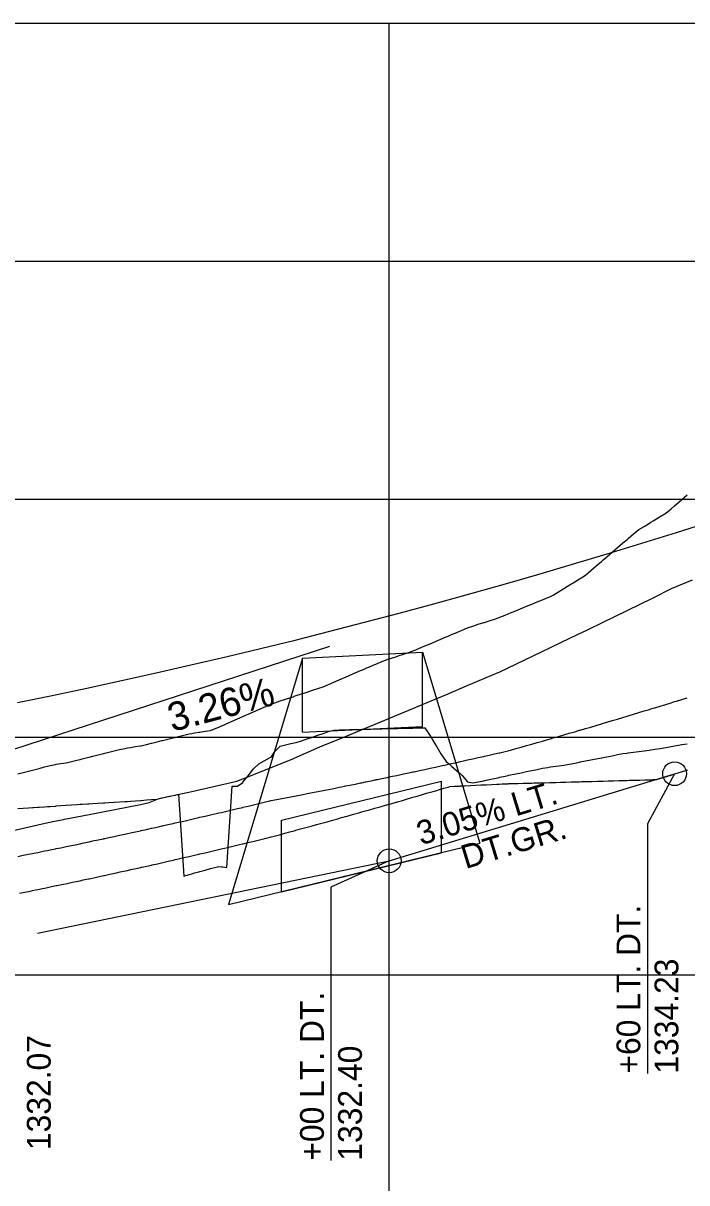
# Model space of a CAD drawing. Extents: x 1371206 to 1374178, y 379328 to 381511.
# Drawn here: x 1372567.7 to 1372707.2, y 379554.7 to 379798.4 of the extents above; entities that cross this region are included whole.
import ezdxf

# ---------------------------------------------------------------- set-up
doc = ezdxf.new("R2010")
doc.units = 0
for name, color, linetype in [('37', 7, 'Continuous'), ('R_Exist Surface', 7, 'Continuous'), ('R_Profile Work Left', 7, 'Continuous'), ('R_Profile Work Right', 7, 'Continuous'), ('R_Vert Alg', 7, 'Continuous'), ('R_Vert Alg Annot', 7, 'Continuous')]:
    doc.layers.add(name, color=color, linetype=linetype)

msp = doc.modelspace()

# ---------------------------------------------------------------- linework, layer by layer
at = {"layer": '37'}
for p, q in [((1371244.63, 379798.35), (1374144.63, 379798.35)), ((1371244.63, 379798.35), (1374144.63, 379798.35)), ((1372644.63, 379348.35), (1372644.63, 379798.35)), ((1371244.63, 379748.35), (1374144.63, 379748.35)), ((1371244.63, 379698.35), (1374144.63, 379698.35)), ((1371244.63, 379648.35), (1374144.63, 379648.35)), ((1371244.63, 379598.35), (1372944.63, 379598.35)), ((1371244.63, 379598.35), (1374144.63, 379598.35))]:
    msp.add_line(p, q, dxfattribs=at)
at = {"layer": 'R_Exist Surface'}
msp.add_lwpolyline([(1372560.01, 379627.48), (1372570.79, 379629.89), (1372573.58, 379630.53), (1372576.16, 379631.02), (1372576.38, 379631.07), (1372581.56, 379632.08), (1372592.34, 379634.21), (1372594.2, 379634.59), (1372596.3, 379635.42), (1372603.11, 379636.93), (1372612.61, 379639.07), (1372613.89, 379639.58), (1372624.59, 379643.86), (1372624.66, 379643.89), (1372630.05, 379646.26), (1372635.44, 379648.46), (1372640.47, 379650.55), (1372645.72, 379652.71), (1372646.21, 379652.92), (1372654.3, 379656.3), (1372656.99, 379657.43), (1372660.89, 379659.08), (1372667.54, 379661.9), (1372667.76, 379662), (1372678.54, 379667.15), (1372682.76, 379669.2), (1372686.44, 379670.97), (1372689.31, 379672.36), (1372700.09, 379677.63), (1372703.95, 379679.54), (1372708.38, 379681.37)], dxfattribs=at)
at = {"layer": 'R_Profile Work Left'}
for p, q in [((1372626.42, 379664.94), (1372610.88, 379613.15)), ((1372626.42, 379664.94), (1372651.63, 379666.17)), ((1372626.42, 379649.34), (1372626.42, 379664.94)), ((1372651.63, 379650.57), (1372651.63, 379666.17)), ((1372651.63, 379666.17), (1372663.67, 379626.02)), ((1372626.42, 379649.34), (1372651.63, 379650.57)), ((1372621.96, 379630.85), (1372655.59, 379639.05)), ((1372655.59, 379624.05), (1372655.59, 379639.05)), ((1372621.96, 379615.85), (1372621.96, 379630.85)), ((1372610.88, 379613.15), (1372663.67, 379626.02)), ((1372621.96, 379615.85), (1372655.59, 379624.05))]:
    msp.add_line(p, q, dxfattribs=at)
for points in [[(1372611.59, 379638.05), (1372612.72, 379638.01), (1372613.84, 379638.81), (1372613.89, 379638.87), (1372614.63, 379639.81), (1372614.97, 379640.23), (1372616.09, 379641.65), (1372617.22, 379642.75), (1372618.34, 379643.35), (1372619.47, 379643.96), (1372619.63, 379644.05), (1372619.79, 379644.14), (1372620.6, 379645.29), (1372621.72, 379646.46), (1372622.85, 379646.72), (1372623.97, 379646.97), (1372624.63, 379647.12), (1372624.66, 379647.13), (1372625.1, 379647.22), (1372626.22, 379647.58), (1372627.35, 379647.96), (1372628.47, 379648.34), (1372629.6, 379648.72), (1372629.63, 379648.73), (1372630.72, 379649.1), (1372631.85, 379649.48), (1372632.97, 379649.82), (1372634.1, 379649.85), (1372634.63, 379649.86), (1372635.23, 379649.88), (1372635.44, 379649.89), (1372636.35, 379649.91), (1372637.48, 379649.94), (1372638.6, 379649.97), (1372638.85, 379649.98), (1372639.63, 379650), (1372639.73, 379650.01), (1372640.85, 379650.04), (1372641.39, 379650.05), (1372641.63, 379650.06), (1372641.83, 379650.06), (1372641.98, 379650.07), (1372642.14, 379650.07), (1372643.1, 379650.09), (1372644.23, 379650.12), (1372644.63, 379650.13), (1372645.35, 379650.15), (1372646.21, 379650.16), (1372646.48, 379650.17), (1372647.6, 379650.2), (1372648.73, 379650.23), (1372649.63, 379650.25), (1372649.86, 379650.26), (1372650.98, 379650.29), (1372652.11, 379650.32), (1372653.23, 379648.59), (1372654.36, 379646.71), (1372654.63, 379646.26), (1372655.48, 379644.84), (1372656.61, 379643.22), (1372656.99, 379642.89), (1372657.73, 379642.25), (1372658.86, 379641.27), (1372659.63, 379640.6), (1372659.98, 379640.3), (1372661.11, 379638.93), (1372662.23, 379638.72), (1372663.36, 379638.94), (1372664.49, 379639.18), (1372664.63, 379639.21), (1372665.61, 379639.42), (1372666.74, 379639.66), (1372667.76, 379639.88), (1372667.86, 379639.9), (1372668.99, 379640.14), (1372669.63, 379640.28), (1372669.79, 379640.31), (1372670.11, 379640.38), (1372671.24, 379640.62), (1372672.36, 379640.85), (1372673.49, 379641.08), (1372674.61, 379641.32), (1372674.63, 379641.32), (1372675.74, 379641.55), (1372676.87, 379641.79), (1372677.99, 379641.98), (1372678.54, 379642.06), (1372679.12, 379642.14), (1372679.63, 379642.22), (1372680.24, 379642.3), (1372681.37, 379642.47), (1372682.49, 379642.66), (1372683.62, 379642.89), (1372684.63, 379643.08), (1372684.74, 379643.11), (1372685.87, 379643.33), (1372686.99, 379643.55), (1372688.12, 379643.77), (1372689.24, 379643.99), (1372689.31, 379644), (1372689.63, 379644.06), (1372690.37, 379644.21), (1372691.5, 379644.43), (1372692.62, 379644.65), (1372693.75, 379644.86), (1372694.63, 379644.98), (1372694.87, 379645.01), (1372696, 379645.17), (1372697.12, 379645.32), (1372698.25, 379645.47), (1372699.37, 379645.62), (1372699.63, 379645.65), (1372700.09, 379645.72), (1372700.5, 379645.77), (1372701.62, 379645.92), (1372702.75, 379646.13), (1372703.87, 379646.33), (1372704.63, 379646.47), (1372705, 379646.54), (1372706.13, 379646.75), (1372707.25, 379646.95)], [(1372566.92, 379615.54), (1372568.04, 379615.76), (1372569.15, 379615.99), (1372569.63, 379616.09), (1372570.27, 379616.22), (1372570.79, 379616.33), (1372571.1, 379616.39), (1372571.38, 379616.45), (1372572.5, 379616.68), (1372573.61, 379616.91), (1372574.63, 379617.12), (1372574.73, 379617.14), (1372575.84, 379617.37), (1372576.96, 379617.61), (1372578.07, 379617.84), (1372579.18, 379618.08), (1372579.63, 379618.17), (1372580.3, 379618.32), (1372581.41, 379618.55), (1372581.56, 379618.59), (1372581.88, 379618.66), (1372582.53, 379618.79), (1372583.64, 379619.03), (1372584.63, 379619.25), (1372584.76, 379619.28), (1372585.87, 379619.52), (1372586.99, 379619.76), (1372588.1, 379620), (1372589.22, 379620.25), (1372589.63, 379620.34), (1372590.33, 379620.5), (1372591.45, 379620.74), (1372592.34, 379620.94), (1372592.56, 379620.99), (1372592.66, 379621.01), (1372593.68, 379621.24), (1372594.63, 379621.45), (1372594.79, 379621.49), (1372595.9, 379621.74), (1372597.02, 379621.99), (1372598.13, 379622.25), (1372599.25, 379622.5), (1372599.63, 379622.59), (1372600.36, 379622.76), (1372601.48, 379623.01), (1372602.59, 379623.27), (1372603.11, 379623.39), (1372603.44, 379623.47), (1372603.71, 379623.53), (1372604.63, 379623.74), (1372604.82, 379623.79), (1372605.94, 379624.05), (1372607.05, 379624.31), (1372608.17, 379624.57), (1372609.28, 379624.83), (1372609.63, 379624.92), (1372610.39, 379625.1), (1372611.51, 379625.36), (1372612.62, 379625.63), (1372613.74, 379625.9), (1372613.89, 379625.93), (1372614.23, 379626.01), (1372614.63, 379626.11), (1372614.85, 379626.16), (1372615.97, 379626.43), (1372617.08, 379626.7), (1372618.2, 379626.98), (1372619.31, 379627.25), (1372619.63, 379627.33), (1372619.79, 379627.37), (1372620.43, 379627.54), (1372621.54, 379627.83), (1372622.66, 379628.13), (1372623.77, 379628.43), (1372624.63, 379628.67), (1372624.66, 379628.67), (1372624.89, 379628.73), (1372625.01, 379628.77), (1372626, 379629.04), (1372627.11, 379629.34), (1372628.23, 379629.64), (1372629.34, 379629.95), (1372629.63, 379630.03), (1372630.46, 379630.26), (1372631.57, 379630.56), (1372632.69, 379630.87), (1372633.8, 379631.18), (1372634.63, 379631.41), (1372634.92, 379631.49), (1372635.44, 379631.64), (1372635.79, 379631.74), (1372636.03, 379631.8), (1372637.15, 379632.12), (1372638.26, 379632.43), (1372638.85, 379632.6), (1372639.38, 379632.74), (1372639.63, 379632.82), (1372639.94, 379632.91), (1372640.49, 379633.06), (1372641.39, 379633.31), (1372641.6, 379633.38), (1372641.63, 379633.38), (1372642.14, 379633.53), (1372642.72, 379633.69), (1372643.83, 379634.01), (1372644.63, 379634.24), (1372644.95, 379634.33), (1372646.06, 379634.65), (1372646.21, 379634.7), (1372646.57, 379634.8), (1372647.18, 379634.97), (1372648.29, 379635.3), (1372649.41, 379635.62), (1372649.63, 379635.69), (1372650.52, 379635.94), (1372651.64, 379636.27), (1372652.75, 379636.6), (1372653.87, 379636.92), (1372654.63, 379637.15), (1372654.98, 379637.25), (1372656.1, 379637.58), (1372656.99, 379637.85), (1372657.21, 379637.91), (1372657.35, 379637.96), (1372658.32, 379638), (1372659.44, 379638.06), (1372659.63, 379638.07), (1372660.55, 379638.11), (1372661.67, 379638.17), (1372662.78, 379638.22), (1372663.9, 379638.28), (1372664.63, 379638.31), (1372665.01, 379638.33), (1372666.13, 379638.38), (1372667.24, 379638.44), (1372667.76, 379638.46), (1372668.36, 379638.49), (1372669.47, 379638.54), (1372669.63, 379638.55), (1372669.79, 379638.56), (1372670.59, 379638.58), (1372671.7, 379638.61), (1372672.82, 379638.64), (1372673.93, 379638.67), (1372674.63, 379638.69), (1372675.04, 379638.7), (1372676.16, 379638.73), (1372677.27, 379638.76), (1372678.39, 379638.79), (1372678.54, 379638.8), (1372679.5, 379638.82), (1372679.63, 379638.83), (1372680.62, 379638.85), (1372681.73, 379638.88), (1372682.85, 379638.91), (1372683.96, 379638.95), (1372684.63, 379638.96), (1372685.08, 379638.98), (1372686.19, 379639.01), (1372687.31, 379639.04), (1372688.42, 379639.07), (1372689.31, 379639.1), (1372689.53, 379639.1), (1372689.63, 379639.1), (1372690.65, 379639.13), (1372691.76, 379639.17), (1372692.88, 379639.2), (1372693.99, 379639.23), (1372694.63, 379639.25), (1372695.11, 379639.26), (1372696.22, 379639.29), (1372697.34, 379639.32), (1372698.45, 379639.36), (1372699.57, 379639.39), (1372699.63, 379639.39), (1372700.09, 379639.4), (1372700.68, 379639.42), (1372700.84, 379639.43), (1372701.8, 379639.72), (1372702.91, 379640.07), (1372704.03, 379640.42), (1372704.63, 379640.61), (1372705.14, 379640.77), (1372706.25, 379641.12), (1372707.37, 379641.47)], [(1372600.34, 379636.33), (1372601.46, 379619.15), (1372602.59, 379619.5), (1372603.11, 379619.64), (1372603.71, 379619.8), (1372604.63, 379620.04), (1372604.84, 379620.1), (1372605.96, 379620.4), (1372607.09, 379620.7), (1372608.22, 379621.01), (1372608.83, 379621.17), (1372609.34, 379621.1), (1372609.63, 379621.06), (1372610.47, 379620.95), (1372611.59, 379638.05)], [(1372566.58, 379633.35), (1372567.7, 379633.42), (1372568.83, 379633.49), (1372569.63, 379633.54), (1372569.95, 379633.56), (1372570.79, 379633.61), (1372571.08, 379633.63), (1372572.2, 379633.69), (1372572.83, 379633.73), (1372573.33, 379633.77), (1372574.45, 379633.86), (1372574.63, 379633.88), (1372575.58, 379633.96), (1372576.7, 379634.04), (1372577.83, 379634.11), (1372578.96, 379634.18), (1372579.63, 379634.22), (1372580.08, 379634.25), (1372581.21, 379634.32), (1372581.56, 379634.34), (1372582.33, 379634.39), (1372583.46, 379634.46), (1372584.58, 379634.53), (1372584.63, 379634.53), (1372584.83, 379634.55), (1372585.71, 379634.6), (1372586.83, 379634.67), (1372587.96, 379634.74), (1372589.08, 379634.81), (1372589.63, 379634.84), (1372590.21, 379634.88), (1372591.33, 379634.95), (1372592.34, 379635.03), (1372592.46, 379635.04), (1372593.59, 379635.13), (1372594.63, 379635.22), (1372594.71, 379635.23), (1372595.84, 379635.32), (1372596.83, 379635.55), (1372596.96, 379635.57), (1372598.09, 379635.83), (1372599.21, 379636.08), (1372599.63, 379636.17), (1372600.34, 379636.33)]]:
    msp.add_lwpolyline(points, dxfattribs=at)
at = {"layer": 'R_Profile Work Right'}
for points in [[(1372566.58, 379640.63), (1372567.7, 379640.91), (1372568.83, 379641.2), (1372569.63, 379641.41), (1372569.95, 379641.49), (1372570.79, 379641.7), (1372571.08, 379641.77), (1372572.2, 379642.06), (1372572.83, 379642.22), (1372573.33, 379642.35), (1372574.45, 379642.59), (1372574.63, 379642.62), (1372575.58, 379642.78), (1372576.7, 379642.96), (1372577.83, 379643.21), (1372578.96, 379643.49), (1372579.63, 379643.66), (1372580.08, 379643.77), (1372581.21, 379644.05), (1372581.56, 379644.14), (1372582.33, 379644.33), (1372583.46, 379644.61), (1372584.58, 379644.89), (1372584.63, 379644.91), (1372584.83, 379644.96), (1372585.71, 379645.17), (1372586.83, 379645.45), (1372587.96, 379645.74), (1372589.08, 379645.97), (1372589.63, 379646.05), (1372590.21, 379646.15), (1372591.33, 379646.33), (1372592.34, 379646.5), (1372592.46, 379646.53), (1372593.59, 379646.8), (1372594.63, 379647.06), (1372594.71, 379647.08), (1372595.84, 379647.35), (1372596.83, 379647.6), (1372596.96, 379647.63), (1372598.09, 379647.9), (1372599.21, 379648.18), (1372599.63, 379648.28), (1372600.34, 379648.45), (1372601.46, 379648.73), (1372602.59, 379649), (1372603.11, 379649.11), (1372603.71, 379649.21), (1372604.63, 379649.35), (1372604.84, 379649.38), (1372605.96, 379649.55), (1372607.09, 379649.73), (1372608.22, 379650.19), (1372608.83, 379650.46), (1372609.34, 379650.68), (1372609.63, 379650.81), (1372610.47, 379651.17), (1372611.59, 379651.67), (1372612.72, 379652.16), (1372613.84, 379652.65), (1372613.89, 379652.67), (1372614.63, 379652.99), (1372614.97, 379653.14), (1372616.09, 379653.63), (1372617.22, 379654.12), (1372618.34, 379654.61), (1372619.47, 379655.1), (1372619.63, 379655.17), (1372619.79, 379655.24), (1372620.6, 379655.55), (1372621.72, 379655.93), (1372622.85, 379656.3), (1372623.97, 379656.68), (1372624.63, 379656.89), (1372624.66, 379656.91), (1372625.1, 379657.05), (1372626.22, 379657.42), (1372627.35, 379657.8), (1372628.47, 379658.17), (1372629.6, 379658.54), (1372629.63, 379658.55), (1372630.72, 379658.92), (1372631.85, 379659.39), (1372632.97, 379659.88), (1372634.1, 379660.37), (1372634.63, 379660.59), (1372635.23, 379660.85), (1372635.44, 379660.94), (1372636.35, 379661.34), (1372637.48, 379661.82), (1372638.6, 379662.3), (1372638.85, 379662.41), (1372639.63, 379662.75), (1372639.73, 379662.79), (1372640.85, 379663.27), (1372641.39, 379663.5), (1372641.63, 379663.61), (1372641.83, 379663.69), (1372641.98, 379663.75), (1372642.14, 379663.82), (1372643.1, 379664.24), (1372644.23, 379664.65), (1372644.63, 379664.78), (1372645.35, 379665.02), (1372646.21, 379665.3), (1372646.48, 379665.38), (1372647.6, 379665.75), (1372648.73, 379666.12), (1372649.63, 379666.45), (1372649.86, 379666.54), (1372650.98, 379667.02), (1372652.11, 379667.5), (1372653.23, 379667.97), (1372654.36, 379668.45), (1372654.63, 379668.56), (1372655.48, 379668.92), (1372656.61, 379669.4), (1372656.99, 379669.56), (1372657.73, 379669.87), (1372658.86, 379670.35), (1372659.63, 379670.67), (1372659.98, 379670.82), (1372661.11, 379671.3), (1372662.23, 379671.68), (1372663.36, 379672.04), (1372664.49, 379672.4), (1372664.63, 379672.45), (1372665.61, 379672.77), (1372666.74, 379673.13), (1372667.76, 379673.47), (1372667.86, 379673.51), (1372668.99, 379673.98), (1372669.63, 379674.25), (1372669.79, 379674.31), (1372670.11, 379674.44), (1372671.24, 379674.9), (1372672.36, 379675.36), (1372673.49, 379675.82), (1372674.61, 379676.28), (1372674.63, 379676.28), (1372675.74, 379676.73), (1372676.87, 379677.19), (1372677.99, 379677.65), (1372678.54, 379677.87), (1372679.12, 379678.16), (1372679.63, 379678.48), (1372680.24, 379678.86), (1372681.37, 379679.55), (1372682.49, 379680.24), (1372683.62, 379680.94), (1372684.63, 379681.56), (1372684.74, 379681.63), (1372685.87, 379682.37), (1372686.99, 379683.34), (1372688.12, 379684.31), (1372689.24, 379685.27), (1372689.31, 379685.33), (1372689.63, 379685.6), (1372690.37, 379686.24), (1372691.5, 379687.2), (1372692.62, 379688.17), (1372693.75, 379689.13), (1372694.63, 379689.89), (1372694.87, 379690.1), (1372696, 379691.06), (1372697.12, 379691.93), (1372698.25, 379692.62), (1372699.37, 379693.31), (1372699.63, 379693.47), (1372700.09, 379693.75), (1372700.5, 379694), (1372701.62, 379694.69), (1372702.75, 379695.38), (1372703.87, 379696.31), (1372704.63, 379696.96), (1372705, 379697.29), (1372706.13, 379698.26), (1372707.25, 379699.24)], [(1372566.58, 379623.27), (1372567.7, 379623.5), (1372568.83, 379623.72), (1372569.63, 379623.89), (1372569.95, 379623.95), (1372570.79, 379624.12), (1372571.08, 379624.18), (1372572.2, 379624.41), (1372572.83, 379624.53), (1372573.33, 379624.64), (1372574.45, 379624.87), (1372574.63, 379624.9), (1372575.58, 379625.1), (1372576.7, 379625.33), (1372577.83, 379625.56), (1372578.96, 379625.8), (1372579.63, 379625.94), (1372580.08, 379626.03), (1372581.21, 379626.27), (1372581.56, 379626.35), (1372582.33, 379626.51), (1372583.46, 379626.75), (1372584.58, 379626.99), (1372584.63, 379627), (1372584.83, 379627.04), (1372585.71, 379627.23), (1372586.83, 379627.47), (1372587.96, 379627.71), (1372589.08, 379627.96), (1372589.63, 379628.08), (1372590.21, 379628.2), (1372591.33, 379628.45), (1372592.34, 379628.67), (1372592.46, 379628.69), (1372593.59, 379628.94), (1372594.63, 379629.17), (1372594.71, 379629.19), (1372595.84, 379629.44), (1372596.83, 379629.66), (1372596.96, 379629.69), (1372598.09, 379629.94), (1372599.21, 379630.2), (1372599.63, 379630.29), (1372600.34, 379630.45), (1372601.46, 379630.7), (1372602.59, 379630.96), (1372603.11, 379631.08), (1372603.71, 379631.22), (1372604.63, 379631.43), (1372604.84, 379631.48), (1372605.96, 379631.73), (1372607.09, 379631.99), (1372608.22, 379632.25), (1372608.83, 379632.4), (1372609.34, 379632.52), (1372609.63, 379632.58), (1372610.47, 379632.78), (1372611.59, 379633.04), (1372612.72, 379633.31), (1372613.84, 379633.57), (1372613.89, 379633.59), (1372614.63, 379633.76), (1372614.97, 379633.84), (1372616.09, 379634.11), (1372617.22, 379634.38), (1372618.34, 379634.65), (1372619.47, 379634.92), (1372619.63, 379634.96), (1372619.79, 379635), (1372620.6, 379635.15), (1372621.72, 379635.36), (1372622.85, 379635.58), (1372623.97, 379635.8), (1372624.63, 379635.93), (1372624.66, 379635.93), (1372625.1, 379636.02), (1372626.22, 379636.24), (1372627.35, 379636.46), (1372628.47, 379636.68), (1372629.6, 379636.9), (1372629.63, 379636.91), (1372630.72, 379637.12), (1372631.85, 379637.35), (1372632.97, 379637.57), (1372634.1, 379637.8), (1372634.63, 379637.91), (1372635.23, 379638.03), (1372635.44, 379638.07), (1372636.35, 379638.25), (1372637.48, 379638.48), (1372638.6, 379638.71), (1372638.85, 379638.76), (1372639.63, 379638.92), (1372639.73, 379638.94), (1372640.85, 379639.18), (1372641.39, 379639.29), (1372641.63, 379639.34), (1372641.83, 379639.38), (1372641.98, 379639.41), (1372642.14, 379639.44), (1372643.1, 379639.64), (1372644.23, 379639.88), (1372644.63, 379639.96), (1372645.35, 379640.12), (1372646.21, 379640.3), (1372646.48, 379640.35), (1372647.6, 379640.59), (1372648.73, 379640.83), (1372649.63, 379641.02), (1372649.86, 379641.07), (1372650.98, 379641.31), (1372652.11, 379641.56), (1372653.23, 379641.8), (1372654.36, 379642.04), (1372654.63, 379642.1), (1372655.48, 379642.29), (1372656.61, 379642.54), (1372656.99, 379642.62), (1372657.73, 379642.78), (1372658.86, 379643.03), (1372659.63, 379643.2), (1372659.98, 379643.28), (1372661.11, 379643.53), (1372662.23, 379643.78), (1372663.36, 379644.03), (1372664.49, 379644.29), (1372664.63, 379644.32), (1372665.61, 379644.54), (1372666.74, 379644.8), (1372667.76, 379645.03), (1372667.86, 379645.05), (1372668.99, 379645.31), (1372669.63, 379645.46), (1372669.79, 379645.5), (1372670.11, 379645.6), (1372671.24, 379645.91), (1372672.36, 379646.23), (1372673.49, 379646.55), (1372674.61, 379646.87), (1372674.63, 379646.88), (1372675.74, 379647.19), (1372676.87, 379647.51), (1372677.99, 379647.84), (1372678.54, 379648), (1372679.12, 379648.16), (1372679.63, 379648.31), (1372680.24, 379648.49), (1372681.37, 379648.81), (1372682.49, 379649.14), (1372683.62, 379649.47), (1372684.63, 379649.77), (1372684.74, 379649.8), (1372685.87, 379650.13), (1372686.99, 379650.46), (1372688.12, 379650.79), (1372689.24, 379651.13), (1372689.31, 379651.15), (1372689.63, 379651.24), (1372690.37, 379651.46), (1372691.5, 379651.8), (1372692.62, 379652.13), (1372693.75, 379652.47), (1372694.63, 379652.74), (1372694.87, 379652.81), (1372696, 379653.15), (1372697.12, 379653.49), (1372698.25, 379653.83), (1372699.37, 379654.17), (1372699.63, 379654.25), (1372700.09, 379654.39), (1372700.5, 379654.52), (1372701.62, 379654.86), (1372702.75, 379655.21), (1372703.87, 379655.55), (1372704.63, 379655.79), (1372705, 379655.9), (1372706.13, 379656.25), (1372707.25, 379656.6)]]:
    msp.add_lwpolyline(points, dxfattribs=at)
at = {"layer": 'R_Vert Alg'}
for p, q in [((1372544.63, 379638.95), (1372632.13, 379667.48)), ((1372644.63, 379622.35), (1372704.63, 379640.65)), ((1372570.69, 379607.13), (1372644.63, 379622.35))]:
    msp.add_line(p, q, dxfattribs=at)
msp.add_lwpolyline([(1372566.51, 379655.58), (1372573.8, 379657.08), (1372581.09, 379658.62), (1372588.38, 379660.2), (1372595.67, 379661.82), (1372602.96, 379663.49), (1372610.26, 379665.19), (1372617.55, 379666.95), (1372624.84, 379668.74), (1372632.13, 379670.58), (1372639.42, 379672.46), (1372646.71, 379674.39), (1372654.01, 379676.36), (1372661.3, 379678.37), (1372668.59, 379680.42), (1372675.88, 379682.52), (1372683.17, 379684.66), (1372690.46, 379686.84), (1372697.76, 379689.07), (1372705.05, 379691.34), (1372712.34, 379693.65), (1372719.63, 379696.01)], dxfattribs=at)
for centre in [(1372704.63, 379640.65), (1372644.63, 379622.35)]:
    msp.add_circle(centre, 2.5, dxfattribs=at)
at = {"layer": 'R_Vert Alg Annot'}
for points in [[(1372704.63, 379640.65), (1372698.91, 379630.08), (1372698.91, 379630.08), (1372698.91, 379577.68)], [(1372644.63, 379622.35), (1372632.39, 379616.83), (1372632.39, 379611.78), (1372632.39, 379559.38)]]:
    msp.add_lwpolyline(points, dxfattribs=at)

# ---------------------------------------------------------------- texts
for s, height, rotation, p in [('3.26%', 6, 14.7946, (1372598.98, 379649.4)), ('3.05% LT.', 5, 16.9617, (1372651.31, 379625.58)), ('DT.GR.', 5, 16.9617, (1372660.67, 379620.59)), ('+60 LT. DT.', 5, 90, (1372697.41, 379577.63)), ('1334.23', 5, 90, (1372705.41, 379577.63)), ('+00 LT. DT.', 5, 90, (1372630.89, 379559.33)), ('1332.07', 5, 90, (1372573.47, 379561.55)), ('1332.40', 5, 90, (1372638.89, 379559.33))]:
    msp.add_text(s, height=height, rotation=rotation, dxfattribs=at).set_placement(p)

doc.saveas('drawing.dxf')
